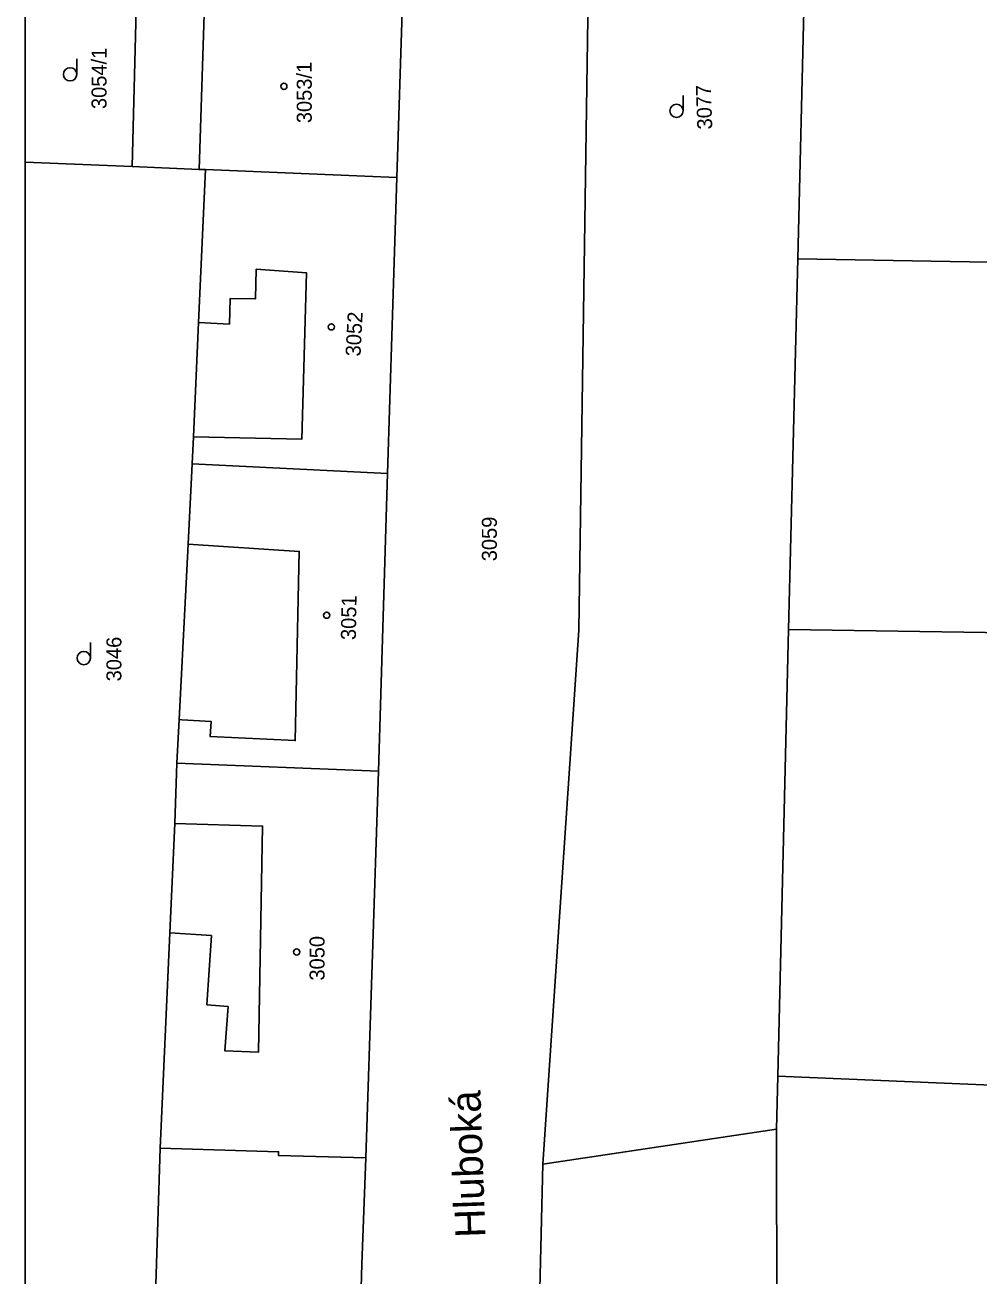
# Model space of a CAD drawing. Extents: x -534410 to -534262, y -1190162 to -1189584.
# Drawn here: x -534410.1 to -534356.1, y -1190081.7 to -1190010.8 of the extents above; entities that cross this region are included whole.
import ezdxf

# ---------------------------------------------------------------- set-up
doc = ezdxf.new("R2010")
doc.units = 0
for name, color, linetype in [('_rámeček', 7, 'Continuous'), ('_rámeček_mřížka', 7, 'Continuous'), ('Hranice parcel', 7, 'Continuous'), ('Parcelní čísla', 7, 'Continuous'), ('Polygon budovy', 7, 'Continuous'), ('Pop  PČ popisy', 7, 'Continuous'), ('Značky budov', 7, 'Continuous'), ('Značky kultur', 7, 'Continuous')]:
    doc.layers.add(name, color=color, linetype=linetype)

msp = doc.modelspace()

# ---------------------------------------------------------------- linework, layer by layer
at = {"layer": '_rámeček'}
msp.add_line((-534410.126, -1189584.47), (-534410.126, -1190161.97), dxfattribs=at)
msp.add_lwpolyline([(-534410.126, -1190004.47), (-534261.626, -1190004.47), (-534261.626, -1190109.47), (-534410.126, -1190109.47)], close=True, dxfattribs=at)
at = {"layer": '_rámeček_mřížka'}
msp.add_line((-534410.126, -1189584.47), (-534410.126, -1190161.97), dxfattribs=at)
at = {"layer": 'Hranice parcel'}
for p, q in [((-534366.35, -1190024.04), (-534365.84, -1190003.05)), ((-534403.8, -1190008.85), (-534404.06, -1190018.82)), ((-534388.75, -1190009.46), (-534389.06, -1190019.44)), ((-534404.06, -1190018.82), (-534410.126, -1190018.573)), ((-534389.06, -1190019.44), (-534399.91, -1190018.99)), ((-534389.59, -1190036.21), (-534389.06, -1190019.44)), ((-534366.87, -1190045.04), (-534366.35, -1190024.04)), ((-534366.35, -1190024.04), (-534342.06, -1190024.47)), ((-534389.59, -1190036.21), (-534400.65, -1190035.66)), ((-534390.11, -1190053.08), (-534389.59, -1190036.21)), ((-534367.49, -1190070.35), (-534366.87, -1190045.04)), ((-534366.87, -1190045.04), (-534342.19, -1190045.44)), ((-534390.11, -1190053.08), (-534401.52, -1190052.62)), ((-534390.83, -1190074.99), (-534390.11, -1190053.08)), ((-534367.56, -1190073.35), (-534367.49, -1190070.35)), ((-534342.37, -1190071.42), (-534367.49, -1190070.35)), ((-534367.56, -1190073.35), (-534380.79, -1190075.34))]:
    msp.add_line(p, q, dxfattribs=at)
for points in [[(-534380.79, -1190075.34), (-534378.76, -1190045.09), (-534377.74, -1189975.71)], [(-534399.91, -1190018.99), (-534400.27, -1190018.98), (-534404.06, -1190018.82)], [(-534400.65, -1190035.66), (-534400.58, -1190034.14), (-534400.29, -1190027.66), (-534399.91, -1190018.99)], [(-534401.52, -1190052.62), (-534401.39, -1190050.15), (-534400.88, -1190040.21), (-534400.65, -1190035.66)], [(-534402.48, -1190074.44), (-534401.92, -1190062.24), (-534401.64, -1190056.04), (-534401.52, -1190052.62)], [(-534367.47, -1190102.26), (-534367.55, -1190076.15), (-534367.56, -1190073.35)], [(-534402.81, -1190084.96), (-534402.74, -1190082.76), (-534402.48, -1190074.44)], [(-534390.83, -1190074.99), (-534395.76, -1190074.86), (-534395.76, -1190074.64), (-534402.48, -1190074.44)], [(-534391.6, -1190100.55), (-534391.1, -1190082.99), (-534391.04, -1190081), (-534390.83, -1190074.99)], [(-534381.06, -1190105.11), (-534381.43, -1190102.09), (-534380.79, -1190075.34)]]:
    msp.add_lwpolyline(points, dxfattribs=at)
at = {"layer": 'Polygon budovy'}
for points in [[(-534399.91, -1190018.99), (-534389.06, -1190019.44), (-534388.75, -1190009.46), (-534399.94, -1190009.01), (-534400.27, -1190018.98)], [(-534400.58, -1190034.14), (-534400.65, -1190035.66), (-534389.59, -1190036.21), (-534389.06, -1190019.44), (-534399.91, -1190018.99), (-534400.29, -1190027.66), (-534398.55, -1190027.75), (-534398.5, -1190026.29), (-534397.07, -1190026.31), (-534397.03, -1190024.64), (-534394.19, -1190024.84), (-534394.44, -1190034.26)], [(-534400.88, -1190040.21), (-534394.59, -1190040.63), (-534394.82, -1190051.34), (-534399.63, -1190051.12), (-534399.58, -1190050.27), (-534401.24, -1190050.16), (-534401.39, -1190050.15), (-534401.52, -1190052.62), (-534390.11, -1190053.08), (-534389.59, -1190036.21), (-534400.65, -1190035.66)], [(-534399.83, -1190066.32), (-534399.57, -1190062.39), (-534401.92, -1190062.24), (-534402.48, -1190074.44), (-534395.76, -1190074.64), (-534395.76, -1190074.86), (-534390.83, -1190074.99), (-534390.11, -1190053.08), (-534401.52, -1190052.62), (-534401.64, -1190056.04), (-534396.67, -1190056.19), (-534396.91, -1190069), (-534398.81, -1190068.92), (-534398.62, -1190066.41)]]:
    msp.add_lwpolyline(points, close=True, dxfattribs=at)
at = {"layer": 'Značky budov'}
for centre in [(-534395.463, -1190014.273), (-534392.773, -1190027.903), (-534393.037, -1190044.241), (-534394.734, -1190063.321)]:
    msp.add_circle(centre, 0.175, dxfattribs=at)
at = {"layer": 'Značky kultur'}
for p, q in [((-534407.198, -1190013.596), (-534407.198, -1190012.721)), ((-534372.846, -1190015.666), (-534372.846, -1190014.791)), ((-534406.424, -1190046.669), (-534406.424, -1190045.794))]:
    msp.add_line(p, q, dxfattribs=at)
for centre in [(-534407.573, -1190013.596), (-534373.221, -1190015.666), (-534406.799, -1190046.669)]:
    msp.add_circle(centre, 0.375, dxfattribs=at)

# ---------------------------------------------------------------- texts
at = {"layer": 'Parcelní čísla'}
for s, rotation, p in [('3054/1', 90, (-534405.508, -1190015.564)), ('3053/1', 90, (-534393.884, -1190016.363)), ('3077', 92, (-534371.192, -1190016.705)), ('3052', 87, (-534391.126, -1190029.594)), ('3059', 90, (-534383.398, -1190041.184)), ('3051', 89, (-534391.387, -1190045.652)), ('3046', 90, (-534404.667, -1190047.989)), ('3050', 90, (-534393.157, -1190064.941))]:
    msp.add_text(s, height=0.85, rotation=rotation, dxfattribs=at).set_placement(p)
at = {"layer": 'Pop  PČ popisy'}
msp.add_text('Hluboká', height=1.7, rotation=92, dxfattribs=at).set_placement((-534384.045, -1190079.482))

doc.saveas('drawing.dxf')
